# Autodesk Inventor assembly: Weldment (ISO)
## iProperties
Length Units: 11269
Angle Units: 11283
Time Units: 11279
Mass Units: 11290
Length Display Precision: 3
Angle Display Precision: 2
Part Number: Weldment (ISO)
Document SubType Name: Weldment
Created: 2002-06
Designer: smithga
Part Number: etrier
Created: 2005-01
Designer: LEGERET Philippe
Material: Aluminum soudé-6061
Control State: 0
Master: False
Shininess: 64.0
Angle Units: 11279
Time Units: 11290
Mass Units: 11283
Compacted: True
Density: 0.0
Volumn: 0.0
Area: 0.0
PropertySet Name: Model Information
Author: LEGERET Philippe
